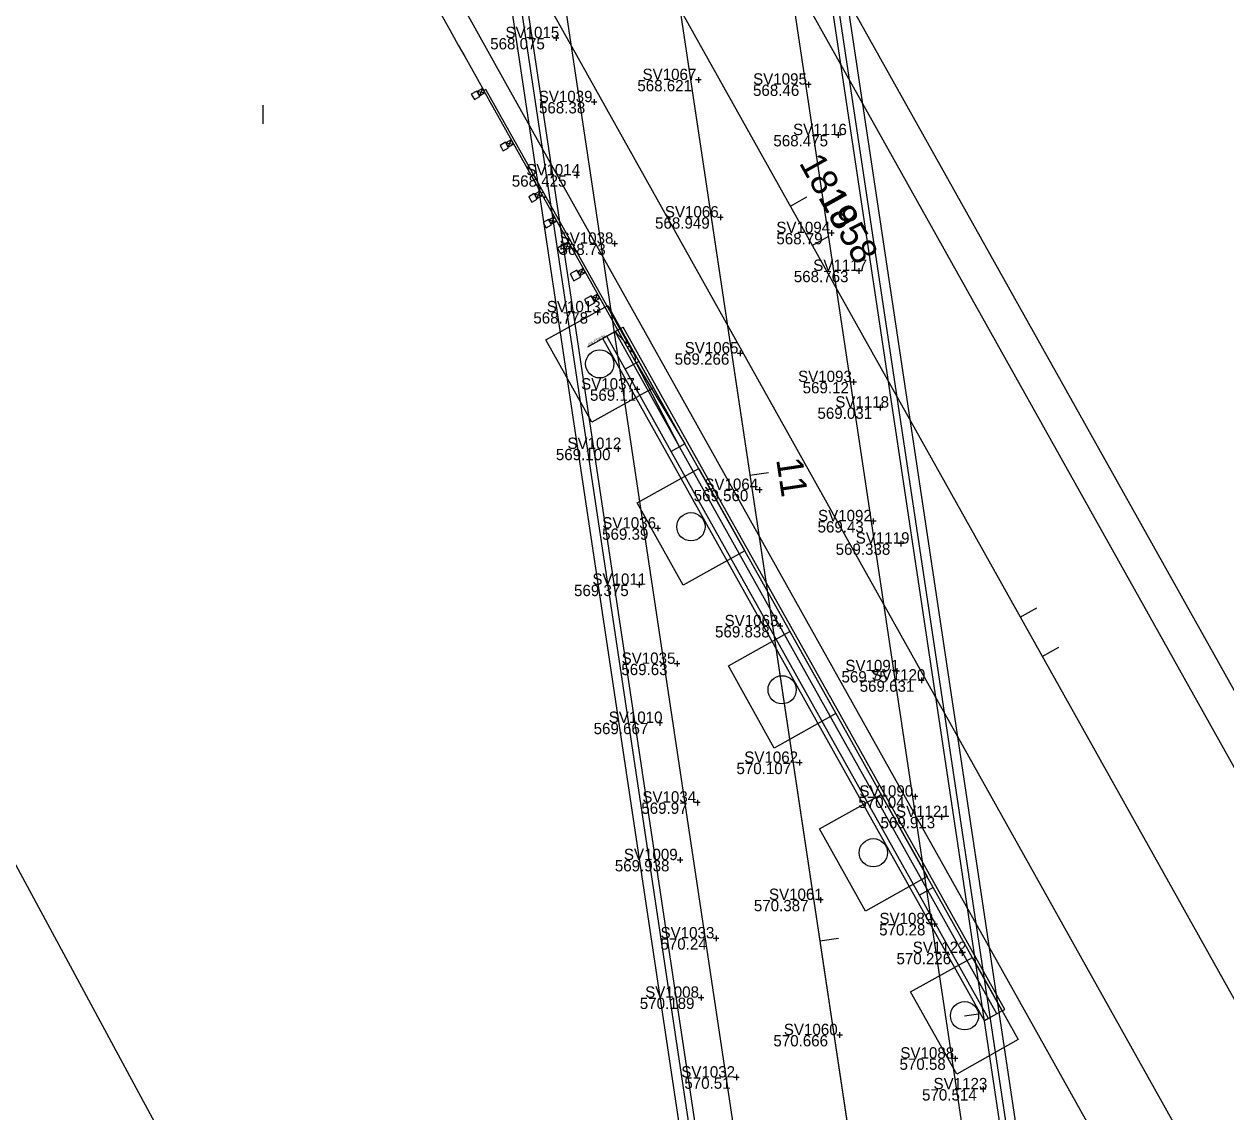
# Model space of a CAD drawing. Extents: x 6334 to 41599, y 9030 to 59113.
# Drawn here: x 21051.8 to 21179.4, y 34246.1 to 34361.6 of the extents above; entities that cross this region are included whole.
import ezdxf

# ---------------------------------------------------------------- set-up
doc = ezdxf.new("R2010")
doc.units = 0
for name, color, linetype in [('BR_P_Rail_Object', 7, 'Continuous'), ('BR_X_Slab_Centerline', 7, 'Continuous'), ('BR_X_SV_Deck_Top', 7, 'Continuous'), ('BR_X_SV_Deck_Top_Text', 7, 'Continuous'), ('BR_X_SV_Pier', 7, 'Continuous'), ('GE_P_CL_20', 7, 'Continuous'), ('GE_X_CL_20', 7, 'Continuous'), ('GK_Visualization', 7, 'Continuous'), ('PM_X_CL_Double_Solid', 7, 'Continuous'), ('PM_X_Lane_Line', 7, 'Continuous'), ('PV_X_EOP', 7, 'Continuous'), ('PV_X_Shoulder', 7, 'Continuous'), ('RD_P_Concrete_Barrier', 7, 'Continuous'), ('RD_P_GR_Rt_Replaced', 7, 'Continuous'), ('RW_X_Esmt_LA', 7, 'Continuous'), ('SC_Scratch1', 7, 'Continuous'), ('SV_X_Shot_Marker', 7, 'Continuous'), ('SV_X_Text_Elevation', 7, 'Continuous'), ('SV_X_Text_Name', 7, 'Continuous')]:
    doc.layers.add(name, color=color, linetype=linetype)

msp = doc.modelspace()

# ---------------------------------------------------------------- linework, layer by layer
at = {"layer": 'BR_P_Rail_Object'}
msp.add_line((21077.16, 34351.01), (21077.17, 34353.01), dxfattribs=at)
at = {"layer": 'BR_X_Slab_Centerline'}
msp.add_line((21088.12, 34584.84), (21156.74, 34127.95), dxfattribs=at)
at = {"layer": 'BR_X_SV_Deck_Top'}
for p, q in [((21072.33, 34570.99), (21124.14, 34226.08)), ((21073.52, 34569.83), (21125.21, 34225.67)), ((21074.44, 34568.18), (21126.13, 34224.03)), ((21118.68, 34489.07), (21170.37, 34144.92)), ((21119.6, 34487.43), (21171.29, 34143.27)), ((21120.67, 34487.02), (21172.48, 34142.11))]:
    msp.add_line(p, q, dxfattribs=at)
at = {"layer": 'BR_X_SV_Deck_Top_Text'}
for p, q in [((21108.57, 34360.13), (21107.97, 34360.13)), ((21108.27, 34360.43), (21108.27, 34359.83)), ((21138.52, 34349.83), (21137.92, 34349.83)), ((21138.22, 34350.13), (21138.22, 34349.53)), ((21110.76, 34345.55), (21110.16, 34345.55)), ((21110.46, 34345.85), (21110.46, 34345.25)), ((21140.71, 34335.41), (21140.11, 34335.41)), ((21140.41, 34335.71), (21140.41, 34335.11)), ((21112.97, 34331.02), (21112.37, 34331.02)), ((21112.67, 34331.32), (21112.67, 34330.72)), ((21142.95, 34320.9), (21142.35, 34320.9)), ((21142.65, 34321.2), (21142.65, 34320.6)), ((21115.14, 34316.51), (21114.54, 34316.51)), ((21114.84, 34316.81), (21114.84, 34316.21)), ((21145.16, 34306.46), (21144.56, 34306.46)), ((21144.86, 34306.76), (21144.86, 34306.16)), ((21117.39, 34302.08), (21116.79, 34302.08)), ((21117.09, 34302.38), (21117.09, 34301.78)), ((21147.34, 34291.92), (21146.74, 34291.92)), ((21147.04, 34292.22), (21147.04, 34291.62)), ((21119.57, 34287.42), (21118.97, 34287.42)), ((21119.27, 34287.72), (21119.27, 34287.12)), ((21149.48, 34277.43), (21148.88, 34277.43)), ((21149.18, 34277.73), (21149.18, 34277.13)), ((21121.72, 34272.85), (21121.12, 34272.85)), ((21121.42, 34273.15), (21121.42, 34272.55)), ((21151.66, 34262.99), (21151.06, 34262.99)), ((21151.36, 34263.29), (21151.36, 34262.69)), ((21123.95, 34258.24), (21123.35, 34258.24)), ((21123.65, 34258.54), (21123.65, 34257.94)), ((21153.89, 34248.52), (21153.29, 34248.52)), ((21153.59, 34248.82), (21153.59, 34248.22))]:
    msp.add_line(p, q, dxfattribs=at)
at = {"layer": 'BR_X_SV_Pier'}
for points in [[(21113.74, 34331.74), (21118.62, 34323.01), (21112.07, 34319.35), (21107.19, 34328.08)], [(21123.41, 34314.43), (21128.3, 34305.7), (21121.75, 34302.04), (21116.87, 34310.77)], [(21133.09, 34297.13), (21137.97, 34288.4), (21131.43, 34284.74), (21126.55, 34293.47)], [(21142.77, 34279.82), (21147.65, 34271.09), (21141.11, 34267.43), (21136.23, 34276.16)], [(21152.45, 34262.52), (21157.33, 34253.79), (21150.79, 34250.13), (21145.9, 34258.85)]]:
    msp.add_lwpolyline(points, close=True, dxfattribs=at)
for centre in [(21112.9, 34325.54), (21122.58, 34308.24), (21132.26, 34290.93), (21141.94, 34273.63), (21151.62, 34256.32)]:
    msp.add_circle(centre, 1.5, dxfattribs=at)
at = {"layer": 'GE_P_CL_20'}
for p, q in [((21128.84, 34313.72), (21130.82, 34314.01)), ((21136.27, 34264.27), (21138.24, 34264.57))]:
    msp.add_line(p, q, dxfattribs=at)
at = {"layer": 'GE_X_CL_20'}
for p, q in [((21120.4, 34365.07), (21585.88, 33532.76)), ((21133.14, 34342.28), (21134.88, 34343.26)), ((21135.46, 34338.12), (21137.21, 34339.1)), ((21157.54, 34298.64), (21159.29, 34299.62)), ((21159.87, 34294.48), (21161.62, 34295.46))]:
    msp.add_line(p, q, dxfattribs=at)
at = {"layer": 'GK_Visualization'}
for p, q in [((21084.27, 34610.45), (21262.51, 33423.7)), ((21084.27, 34610.45), (21262.51, 33423.7)), ((21120.28, 34365.28), (21585.88, 33532.76)), ((21120.4, 34365.07), (21585.88, 33532.76))]:
    msp.add_line(p, q, dxfattribs=at)
at = {"layer": 'PM_X_CL_Double_Solid'}
msp.add_line((21084.27, 34610.45), (21262.51, 33423.7), dxfattribs=at)
at = {"layer": 'PM_X_Lane_Line'}
msp.add_line((21120.4, 34365.07), (21585.88, 33532.76), dxfattribs=at)
msp.add_line((21120.4, 34365.07), (21585.88, 33532.76), dxfattribs=at)
at = {"layer": 'PV_X_EOP'}
for p, q in [((21096.14, 34612.23), (21274.38, 33425.48)), ((21072.4, 34608.67), (21250.65, 33421.92)), ((21130.87, 34370.92), (21596.35, 33538.62)), ((21109.92, 34359.21), (21575.4, 33526.9))]:
    msp.add_line(p, q, dxfattribs=at)
msp.add_arc((24529.94, 36271.9), 3918.53, 191.33607, 209.21667, dxfattribs=at)
at = {"layer": 'PV_X_Shoulder'}
for p, q in [((21134.36, 34372.88), (21599.84, 33540.57)), ((21102.94, 34355.3), (21568.42, 33523))]:
    msp.add_line(p, q, dxfattribs=at)
msp.add_arc((24529.94, 36271.9), 3926.53, 191.34141, 209.21667, dxfattribs=at)
at = {"layer": 'RD_P_Concrete_Barrier'}
for p, q in [((21115.11, 34329.28), (21113.65, 34328.47)), ((21114.52, 34328.96), (21115.46, 34327.97)), ((21121.36, 34316.74), (21114.52, 34328.96)), ((21115.11, 34329.28), (21115.4, 34329.44)), ((21121.94, 34317.06), (21115.11, 34329.28)), ((21122.23, 34317.23), (21115.4, 34329.44)), ((21113.65, 34328.47), (21113.22, 34328.22)), ((21120.05, 34316.01), (21113.22, 34328.22)), ((21120.49, 34316.25), (21113.65, 34328.47)), ((21116.77, 34325.63), (21115.46, 34327.97)), ((21117.06, 34325.79), (21115.6, 34324.98)), ((21116.77, 34325.63), (21121.94, 34317.06)), ((21121.36, 34316.74), (21116.77, 34325.63)), ((21121.94, 34317.06), (21120.49, 34316.25)), ((21137.16, 34286.44), (21120.49, 34316.25)), ((21138.03, 34286.92), (21121.36, 34316.74)), ((21138.62, 34287.25), (21121.94, 34317.06)), ((21138.9, 34287.41), (21122.23, 34317.23)), ((21136.72, 34286.19), (21120.05, 34316.01)), ((21147.72, 34269.61), (21138.03, 34286.92)), ((21148.3, 34269.93), (21138.62, 34287.25)), ((21148.59, 34270.1), (21138.9, 34287.41)), ((21146.41, 34268.88), (21136.72, 34286.19)), ((21146.84, 34269.12), (21137.16, 34286.44)), ((21148.3, 34269.93), (21146.84, 34269.12)), ((21154.17, 34256.03), (21146.84, 34269.12)), ((21155.04, 34256.52), (21147.72, 34269.61)), ((21155.62, 34256.84), (21148.3, 34269.93)), ((21155.91, 34257), (21148.59, 34270.1)), ((21153.73, 34255.78), (21146.41, 34268.88)), ((21155.62, 34256.84), (21154.17, 34256.03)), ((21155.62, 34256.84), (21155.91, 34257)), ((21154.17, 34256.03), (21153.73, 34255.78))]:
    msp.add_line(p, q, dxfattribs=at)
at = {"layer": 'RD_P_GR_Rt_Replaced'}
for p, q in [((21099.88, 34354.45), (21100.71, 34354.34)), ((21100.46, 34354.77), (21100.13, 34354.01)), ((21100.8, 34354.68), (21100.59, 34354.56)), ((21116.77, 34325.63), (21100.59, 34354.56)), ((21116.61, 34326.42), (21100.8, 34354.68)), ((21103.18, 34348.56), (21103.51, 34349.32)), ((21102.93, 34348.99), (21103.76, 34348.88)), ((21106.61, 34344.29), (21106.39, 34344.17)), ((21105.98, 34343.54), (21106.81, 34343.43)), ((21106.23, 34343.1), (21106.57, 34343.86)), ((21106.91, 34343.77), (21106.69, 34343.65)), ((21107.2, 34343.24), (21106.98, 34343.12)), ((21107.51, 34340.81), (21108.33, 34340.7)), ((21107.75, 34340.37), (21108.09, 34341.14)), ((21109.03, 34338.08), (21109.86, 34337.97)), ((21109.28, 34337.65), (21109.62, 34338.41)), ((21109.66, 34338.84), (21109.45, 34338.71)), ((21109.96, 34338.31), (21109.74, 34338.19)), ((21110.25, 34337.79), (21110.03, 34337.67)), ((21110.56, 34335.36), (21111.39, 34335.25)), ((21110.8, 34334.92), (21111.14, 34335.68)), ((21112.33, 34332.19), (21112.67, 34332.95)), ((21112.09, 34332.63), (21112.91, 34332.52)), ((21114.81, 34329.12), (21111.6, 34327.32)), ((21115.76, 34327.93), (21115.55, 34327.8)), ((21116.06, 34327.4), (21115.84, 34327.28)), ((21116.35, 34326.88), (21116.13, 34326.76)), ((21116.8, 34325.64), (21116.67, 34325.86)), ((21116.8, 34325.64), (21116.77, 34325.63))]:
    msp.add_line(p, q, dxfattribs=at)
for points in [[(21099.26, 34354.19), (21099.59, 34353.61), (21100.17, 34353.93), (21099.85, 34354.51)], [(21099.88, 34354.45), (21100.13, 34354.01), (21100.71, 34354.34), (21100.46, 34354.77)], [(21102.93, 34348.99), (21103.18, 34348.56), (21103.76, 34348.88), (21103.51, 34349.32)], [(21102.31, 34348.74), (21102.64, 34348.16), (21103.22, 34348.48), (21102.89, 34349.07)], [(21105.36, 34343.29), (21105.69, 34342.7), (21106.27, 34343.03), (21105.94, 34343.61)], [(21105.98, 34343.54), (21106.23, 34343.1), (21106.81, 34343.43), (21106.57, 34343.86)], [(21106.89, 34340.56), (21107.21, 34339.98), (21107.79, 34340.3), (21107.47, 34340.88)], [(21107.51, 34340.81), (21107.75, 34340.37), (21108.33, 34340.7), (21108.09, 34341.14)], [(21108.41, 34337.83), (21108.74, 34337.25), (21109.32, 34337.57), (21108.99, 34338.16)], [(21109.03, 34338.08), (21109.28, 34337.65), (21109.86, 34337.97), (21109.62, 34338.41)], [(21109.75, 34335.09), (21110.16, 34334.37), (21110.89, 34334.77), (21110.48, 34335.5)], [(21110.56, 34335.36), (21110.8, 34334.92), (21111.39, 34335.25), (21111.14, 34335.68)], [(21111.28, 34332.37), (21111.68, 34331.64), (21112.41, 34332.05), (21112, 34332.77)], [(21112.09, 34332.63), (21112.33, 34332.19), (21112.91, 34332.52), (21112.67, 34332.95)]]:
    msp.add_lwpolyline(points, close=True, dxfattribs=at)
for centre, radius, start, end in [((24529.93, 36271.95), 3928.97, 207.9175, 209.21019), ((21116.02, 34326.07), 0.684, 342.4251, 31.1679)]:
    msp.add_arc(centre, radius, start, end, dxfattribs=at)
for centre in [(21106.57, 34344.11), (21107.04, 34343.28), (21109.62, 34338.66), (21110.09, 34337.83), (21115.73, 34327.75), (21116.19, 34326.92)]:
    msp.add_ellipse(centre, major_axis=(0.0185, -0.033), ratio=0.460352, dxfattribs=at)
at = {"layer": 'RW_X_Esmt_LA'}
msp.add_line((21020.77, 34328.02), (21084.66, 34209.87), dxfattribs=at)
at = {"layer": 'SC_Scratch1'}
msp.add_line((21151.62, 34256.32), (21153.1, 34256.54), dxfattribs=at)
at = {"layer": 'SV_X_Shot_Marker'}
for p, q in [((21123.68, 34355.68), (21123.08, 34355.68)), ((21123.38, 34355.98), (21123.38, 34355.38)), ((21135.35, 34355.19), (21134.75, 34355.19)), ((21135.05, 34355.49), (21135.05, 34354.89)), ((21112.59, 34353.33), (21111.99, 34353.33)), ((21112.29, 34353.63), (21112.29, 34353.03)), ((21126, 34341.09), (21125.4, 34341.09)), ((21125.7, 34341.39), (21125.7, 34340.79)), ((21137.79, 34339.43), (21137.19, 34339.43)), ((21137.49, 34339.73), (21137.49, 34339.13)), ((21114.77, 34338.3), (21114.17, 34338.3)), ((21114.47, 34338.6), (21114.47, 34338)), ((21128.09, 34326.65), (21127.49, 34326.65)), ((21127.79, 34326.95), (21127.79, 34326.35)), ((21139.84, 34323.91), (21139.84, 34323.31)), ((21117.16, 34322.82), (21116.56, 34322.82)), ((21116.86, 34323.12), (21116.86, 34322.52)), ((21140.14, 34323.61), (21139.54, 34323.61)), ((21129.85, 34312.46), (21129.85, 34311.86)), ((21130.15, 34312.16), (21129.55, 34312.16)), ((21142.23, 34308.83), (21141.63, 34308.83)), ((21141.93, 34309.13), (21141.93, 34308.53)), ((21119.35, 34308.06), (21118.75, 34308.06)), ((21119.05, 34308.36), (21119.05, 34307.76)), ((21132.34, 34297.69), (21131.74, 34297.69)), ((21132.04, 34297.99), (21132.04, 34297.39)), ((21121.4, 34293.69), (21120.8, 34293.69)), ((21121.1, 34293.99), (21121.1, 34293.39)), ((21144.43, 34293.21), (21144.43, 34292.61)), ((21144.73, 34292.91), (21144.13, 34292.91)), ((21134.39, 34283.18), (21133.79, 34283.18)), ((21134.09, 34283.48), (21134.09, 34282.88)), ((21123.27, 34279.26), (21123.27, 34278.66)), ((21146.67, 34279.59), (21146.08, 34279.59)), ((21146.38, 34279.89), (21146.38, 34279.29)), ((21123.57, 34278.96), (21122.97, 34278.96)), ((21136.32, 34268.92), (21136.32, 34268.32)), ((21136.62, 34268.62), (21136.02, 34268.62)), ((21148.74, 34266.05), (21148.14, 34266.05)), ((21148.44, 34266.35), (21148.44, 34265.75)), ((21125.54, 34264.54), (21124.94, 34264.54)), ((21125.24, 34264.84), (21125.24, 34264.24)), ((21138.66, 34254.27), (21138.06, 34254.27)), ((21138.36, 34254.57), (21138.36, 34253.97)), ((21150.92, 34251.78), (21150.32, 34251.78)), ((21150.62, 34252.08), (21150.62, 34251.48)), ((21127.41, 34250.07), (21127.41, 34249.47)), ((21127.71, 34249.77), (21127.11, 34249.77))]:
    msp.add_line(p, q, dxfattribs=at)

# ---------------------------------------------------------------- texts
at = {"layer": 'BR_X_SV_Deck_Top_Text'}
for s, p in [('SV1015', (21102.89, 34360.13)), ('568.075', (21101.27, 34358.93)), ('SV1116', (21133.42, 34349.83)), ('568.475', (21131.33, 34348.63)), ('SV1014', (21105.1, 34345.55)), ('568.425', (21103.56, 34344.35)), ('SV1117', (21135.56, 34335.41)), ('568.763', (21133.5, 34334.21)), ('SV1013', (21107.28, 34331.02)), ('568.778', (21105.85, 34329.82)), ('SV1118', (21137.9, 34320.9)), ('569.031', (21136.01, 34319.7)), ('SV1012', (21109.47, 34316.51)), ('569.100', (21108.24, 34315.31)), ('SV1119', (21140.07, 34306.46)), ('569.338', (21137.94, 34305.26)), ('569.375', (21110.17, 34300.88)), ('SV1011', (21112.12, 34302.08)), ('569.631', (21140.49, 34290.72)), ('SV1120', (21141.75, 34291.92)), ('SV1010', (21113.85, 34287.42)), ('569.667', (21112.25, 34286.22)), ('SV1121', (21144.35, 34277.43)), ('569.913', (21142.7, 34276.23)), ('SV1009', (21115.46, 34272.85)), ('569.938', (21114.5, 34271.65)), ('SV1122', (21146.12, 34262.99)), ('570.226', (21144.4, 34261.79)), ('SV1008', (21117.72, 34258.24)), ('570.189', (21117.15, 34257.04)), ('570.514', (21147.11, 34247.32)), ('SV1123', (21148.33, 34248.52))]:
    msp.add_text(s, height=1.2, dxfattribs=at).set_placement(p)
at = {"layer": 'GE_P_CL_20'}
msp.add_text('11', height=2.8, rotation=278.5417, dxfattribs=at).set_placement((21131.62, 34315.39))
at = {"layer": 'GE_X_CL_20'}
for s, p in [('1819', (21134, 34346.88)), ('1858', (21136.08, 34343.17))]:
    msp.add_text(s, height=2.8, rotation=299.2167, dxfattribs=at).set_placement(p)
at = {"layer": 'RD_P_GR_Rt_Replaced'}
msp.add_text('end of barrier', height=0.25, rotation=29.2167, dxfattribs=at).set_placement((21111.69, 34327.47))
at = {"layer": 'SV_X_Text_Elevation'}
for s, p in [('568.621', (21116.89, 34354.48)), ('568.46', (21129.17, 34353.99)), ('568.38', (21106.45, 34352.13)), ('568.949', (21118.77, 34339.89)), ('568.79', (21131.65, 34338.23)), ('568.73', (21108.62, 34337.1)), ('569.266', (21120.85, 34325.45)), ('569.11', (21111.86, 34321.62)), ('569.12', (21134.44, 34322.41)), ('569.560', (21122.87, 34310.96)), ('569.43', (21136.02, 34307.63)), ('569.39', (21113.15, 34306.86)), ('569.838', (21125.14, 34296.49)), ('569.63', (21115.19, 34292.49)), ('569.75', (21138.56, 34291.71)), ('570.107', (21127.41, 34281.98)), ('570.04', (21140.35, 34278.39)), ('569.97', (21117.31, 34277.76)), ('570.387', (21129.26, 34267.42)), ('570.28', (21142.56, 34264.85)), ('570.24', (21119.34, 34263.34)), ('570.666', (21131.33, 34253.07)), ('570.58', (21144.72, 34250.58)), ('570.51', (21121.88, 34248.57))]:
    msp.add_text(s, height=1.2, dxfattribs=at).set_placement(p)
at = {"layer": 'SV_X_Text_Name'}
for s, p in [('SV1067', (21117.44, 34355.68)), ('SV1095', (21129.18, 34355.19)), ('SV1039', (21106.42, 34353.33)), ('SV1066', (21119.81, 34341.09)), ('SV1094', (21131.64, 34339.43)), ('SV1038', (21108.64, 34338.3)), ('SV1065', (21121.91, 34326.65)), ('SV1037', (21110.92, 34322.82)), ('SV1093', (21133.95, 34323.61)), ('SV1064', (21124, 34312.16)), ('SV1092', (21136.07, 34308.83)), ('SV1036', (21113.16, 34308.06)), ('SV1063', (21126.15, 34297.69)), ('SV1035', (21115.22, 34293.69)), ('SV1091', (21138.97, 34292.91)), ('SV1062', (21128.24, 34283.18)), ('SV1090', (21140.46, 34279.59)), ('SV1034', (21117.42, 34278.96)), ('SV1061', (21130.86, 34268.62)), ('SV1089', (21142.59, 34266.05)), ('SV1033', (21119.35, 34264.54)), ('SV1060', (21132.44, 34254.27)), ('SV1088', (21144.81, 34251.78)), ('SV1032', (21121.55, 34249.77))]:
    msp.add_text(s, height=1.2, dxfattribs=at).set_placement(p)

doc.saveas('drawing.dxf')
